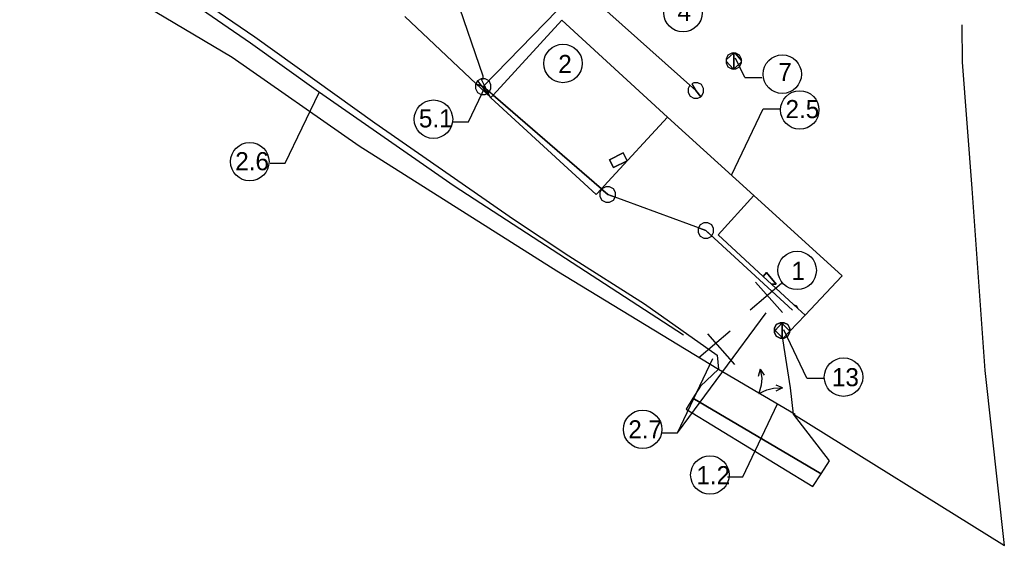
# Model space of a CAD drawing. Extents: x -438410 to -437811, y -1133174 to -1132817.
# Drawn here: x -438410 to -438308.1, y -1133171.7 to -1133117.4 of the extents above; entities that cross this region are included whole.
import ezdxf

# ---------------------------------------------------------------- set-up
doc = ezdxf.new("R2010")
doc.units = 0
for name, color, linetype in [('11 - bourané objekty', 7, 'Continuous'), ('17 - panel', 7, 'Continuous'), ('18 - asfalt', 7, 'Continuous'), ('2 - dopravní značení', 7, 'Continuous'), ('20 - popisy', 7, 'Continuous'), ('3 - ploty a brány', 7, 'Continuous'), ('4 - svodidla', 7, 'Continuous'), ('5 - obrubníky', 7, 'Continuous'), ('7 - elektro', 7, 'Continuous')]:
    doc.layers.add(name, color=color, linetype=linetype)

msp = doc.modelspace()

# ---------------------------------------------------------------- linework, layer by layer
at = {"layer": '11 - bourané objekty'}
for p, q in [((-438353.87, -1133117.4), (-438360.99, -1133125.16)), ((-438336.12, -1133120.84), (-438336.88, -1133121.51)), ((-438336.88, -1133121.51), (-438336.12, -1133120.84)), ((-438336.68, -1133121.04), (-438336.88, -1133121.44)), ((-438336.28, -1133120.84), (-438336.68, -1133121.04)), ((-438336.12, -1133120.84), (-438336.28, -1133120.84)), ((-438336.03, -1133120.76), (-438336.12, -1133120.84)), ((-438336.08, -1133120.84), (-438336.12, -1133120.84)), ((-438336.08, -1133121.49), (-438336.08, -1133120.84)), ((-438336.03, -1133120.84), (-438336.03, -1133120.76)), ((-438335.88, -1133120.84), (-438335.95, -1133120.84)), ((-438335.95, -1133120.84), (-438335.28, -1133121.58)), ((-438335.28, -1133121.58), (-438335.95, -1133120.84)), ((-438335.48, -1133121.04), (-438335.88, -1133120.84)), ((-438335.28, -1133121.44), (-438335.48, -1133121.04)), ((-438336.88, -1133121.44), (-438336.88, -1133121.51)), ((-438336.88, -1133121.67), (-438336.15, -1133122.44)), ((-438336.15, -1133122.44), (-438336.88, -1133121.67)), ((-438336.88, -1133121.67), (-438336.88, -1133121.84)), ((-438336.88, -1133121.84), (-438336.68, -1133122.24)), ((-438336.08, -1133122.44), (-438336.08, -1133121.79)), ((-438336.02, -1133122.44), (-438335.28, -1133121.74)), ((-438335.28, -1133121.74), (-438336.02, -1133122.44)), ((-438335.48, -1133122.24), (-438335.28, -1133121.84)), ((-438335.28, -1133121.58), (-438335.28, -1133121.44)), ((-438335.28, -1133121.84), (-438335.28, -1133121.74)), ((-438336.68, -1133122.24), (-438336.28, -1133122.44)), ((-438336.28, -1133122.44), (-438336.15, -1133122.44)), ((-438336.15, -1133122.44), (-438336.09, -1133122.5)), ((-438336.09, -1133122.44), (-438336.15, -1133122.44)), ((-438336.09, -1133122.5), (-438336.09, -1133122.44)), ((-438336.08, -1133122.44), (-438336.02, -1133122.44)), ((-438336.02, -1133122.44), (-438335.88, -1133122.44)), ((-438335.88, -1133122.44), (-438335.48, -1133122.24)), ((-438360.99, -1133125.16), (-438361.23, -1133125.42)), ((-438360.99, -1133125.16), (-438349.78, -1133134.87)), ((-438349.78, -1133134.87), (-438360.99, -1133125.16)), ((-438348.92, -1133131.85), (-438347.52, -1133131.15)), ((-438347.52, -1133131.15), (-438348.92, -1133131.85)), ((-438347.52, -1133131.15), (-438347.12, -1133131.95)), ((-438347.12, -1133131.95), (-438347.52, -1133131.15)), ((-438348.52, -1133132.65), (-438348.92, -1133131.85)), ((-438348.92, -1133131.85), (-438348.52, -1133132.65)), ((-438347.12, -1133131.95), (-438348.52, -1133132.65)), ((-438348.52, -1133132.65), (-438347.12, -1133131.95)), ((-438350.32, -1133135.46), (-438349.78, -1133134.87)), ((-438324.87, -1133143.87), (-438333.99, -1133135.56)), ((-438337.69, -1133139.63), (-438333.03, -1133143.93)), ((-438333.03, -1133143.93), (-438332.69, -1133143.53)), ((-438332.69, -1133143.53), (-438333.03, -1133143.93)), ((-438332.69, -1133143.53), (-438331.69, -1133144.73)), ((-438331.69, -1133144.73), (-438332.69, -1133143.53)), ((-438331.69, -1133144.73), (-438332.17, -1133144.73)), ((-438332.17, -1133144.73), (-438329.91, -1133146.81)), ((-438332.16, -1133144.73), (-438331.69, -1133144.73)), ((-438329.91, -1133146.81), (-438329.57, -1133146.97)), ((-438329.57, -1133146.97), (-438329.44, -1133147.23)), ((-438331.87, -1133149.29), (-438331.88, -1133149.31)), ((-438331.88, -1133149.31), (-438331.88, -1133149.53)), ((-438331.88, -1133149.53), (-438331.88, -1133149.71)), ((-438331.68, -1133148.91), (-438331.86, -1133149.28)), ((-438331.86, -1133149.28), (-438331.86, -1133149.3)), ((-438331.81, -1133149.53), (-438331.11, -1133148.77)), ((-438331.81, -1133149.53), (-438331.08, -1133150.25)), ((-438331.08, -1133150.25), (-438331.81, -1133149.53)), ((-438331.28, -1133148.71), (-438331.68, -1133148.91)), ((-438331.11, -1133148.71), (-438331.28, -1133148.71)), ((-438331.08, -1133148.8), (-438331.11, -1133148.77)), ((-438330.88, -1133148.71), (-438331.08, -1133148.71)), ((-438330.28, -1133149.58), (-438331.08, -1133148.8)), ((-438331.08, -1133149.36), (-438331.08, -1133148.8)), ((-438331.08, -1133148.8), (-438330.28, -1133149.58)), ((-438331.08, -1133149.51), (-438331.08, -1133149.36)), ((-438331.08, -1133149.66), (-438331.08, -1133149.51)), ((-438330.97, -1133150.31), (-438330.28, -1133149.6)), ((-438330.28, -1133149.6), (-438330.97, -1133150.31)), ((-438330.48, -1133148.91), (-438330.88, -1133148.71)), ((-438330.28, -1133149.31), (-438330.48, -1133148.91)), ((-438330.28, -1133149.58), (-438330.28, -1133149.31)), ((-438330.28, -1133149.71), (-438330.28, -1133149.6)), ((-438331.88, -1133149.71), (-438331.68, -1133150.11)), ((-438331.68, -1133150.11), (-438331.28, -1133150.31)), ((-438331.28, -1133150.31), (-438331.08, -1133150.31)), ((-438331.08, -1133150.25), (-438331.08, -1133149.66)), ((-438331.08, -1133150.25), (-438331.02, -1133150.31)), ((-438331.08, -1133150.31), (-438331.08, -1133150.25)), ((-438330.97, -1133150.31), (-438330.88, -1133150.31)), ((-438330.88, -1133150.31), (-438330.48, -1133150.11)), ((-438330.48, -1133150.11), (-438330.28, -1133149.71))]:
    msp.add_line(p, q, dxfattribs=at)
for points in [[(-438342.94, -1133127.44), (-438342.94, -1133127.44), (-438353.87, -1133117.4)], [(-438336.12, -1133120.84), (-438336.08, -1133120.84), (-438336.03, -1133120.84)], [(-438335.95, -1133120.84), (-438336.03, -1133120.84), (-438336.08, -1133120.84)], [(-438336.08, -1133120.84), (-438336.08, -1133121.49), (-438336.08, -1133121.64), (-438336.08, -1133121.79), (-438336.08, -1133122.44)], [(-438336.88, -1133121.51), (-438336.88, -1133121.59), (-438336.88, -1133121.67)], [(-438336.08, -1133121.79), (-438336.08, -1133121.64), (-438336.08, -1133121.49)], [(-438336.08, -1133121.49), (-438336.08, -1133121.49)], [(-438336.08, -1133121.79), (-438336.08, -1133121.79)], [(-438335.28, -1133121.74), (-438335.28, -1133121.67), (-438335.28, -1133121.58)], [(-438336.15, -1133122.44), (-438336.09, -1133122.44), (-438336.08, -1133122.44)], [(-438361.23, -1133125.42), (-438361.23, -1133125.42), (-438361.23, -1133125.42), (-438361.23, -1133125.42)], [(-438361.23, -1133125.42), (-438361.22, -1133125.44), (-438350.32, -1133135.45), (-438350.32, -1133135.46)], [(-438349.78, -1133134.87), (-438349.12, -1133134.15), (-438342.94, -1133127.44)], [(-438342.94, -1133127.44), (-438342.94, -1133127.44), (-438342.94, -1133127.44)], [(-438333.99, -1133135.56), (-438333.99, -1133135.56), (-438337.69, -1133139.62)], [(-438337.69, -1133139.62), (-438337.69, -1133139.63), (-438337.69, -1133139.63), (-438337.69, -1133139.63)], [(-438333.03, -1133143.93), (-438333.03, -1133143.93), (-438332.16, -1133144.72), (-438332.16, -1133144.73)], [(-438328.69, -1133147.93), (-438324.88, -1133143.88), (-438324.87, -1133143.87)], [(-438324.87, -1133143.87), (-438324.87, -1133143.87), (-438324.87, -1133143.87)], [(-438329.44, -1133147.23), (-438328.69, -1133147.92), (-438328.69, -1133147.93)], [(-438331.88, -1133149.53), (-438331.81, -1133149.53), (-438331.81, -1133149.53)], [(-438331.81, -1133149.53), (-438331.81, -1133149.53), (-438331.88, -1133149.53)], [(-438331.86, -1133149.3), (-438331.87, -1133149.29)], [(-438331.12, -1133148.77), (-438331.81, -1133149.53), (-438331.81, -1133149.53)], [(-438331.81, -1133149.53), (-438331.81, -1133149.53), (-438331.81, -1133149.53)], [(-438331.11, -1133148.77), (-438331.11, -1133148.77), (-438331.12, -1133148.77)], [(-438331.11, -1133148.77), (-438331.11, -1133148.77), (-438331.11, -1133148.71)], [(-438331.08, -1133148.71), (-438331.08, -1133148.77), (-438331.08, -1133148.8)], [(-438331.08, -1133148.8), (-438331.08, -1133149.36), (-438331.08, -1133149.51), (-438331.08, -1133149.66), (-438331.08, -1133150.25)], [(-438330.28, -1133149.6), (-438330.28, -1133149.6), (-438330.28, -1133149.58)], [(-438331.02, -1133150.31), (-438330.99, -1133150.31), (-438330.97, -1133150.31)]]:
    msp.add_lwpolyline(points, dxfattribs=at)
at = {"layer": '17 - panel'}
for p, q in [((-438362, -1133123.21), (-438364.86, -1133114.9)), ((-438370.13, -1133117.02), (-438362.75, -1133123.99)), ((-438362.75, -1133123.99), (-438362.6, -1133123.69)), ((-438362.2, -1133123.49), (-438362, -1133123.49)), ((-438362, -1133123.49), (-438362, -1133123.21))]:
    msp.add_line(p, q, dxfattribs=at)
msp.add_lwpolyline([(-438362.6, -1133123.69), (-438361.24, -1133125.42), (-438362.2, -1133123.49)], dxfattribs=at)
at = {"layer": '18 - asfalt'}
for p, q in [((-438362.75, -1133123.99), (-438370.13, -1133117.02)), ((-438385.64, -1133119.14), (-438373.21, -1133128.04)), ((-438361.23, -1133125.42), (-438362.75, -1133123.99)), ((-438373.21, -1133128.04), (-438358.87, -1133138.01)), ((-438333.99, -1133135.56), (-438342.94, -1133127.44)), ((-438349.78, -1133134.87), (-438350.32, -1133135.45)), ((-438337.69, -1133139.62), (-438333.99, -1133135.56)), ((-438358.87, -1133138.01), (-438353.15, -1133141.78)), ((-438333.03, -1133143.93), (-438337.69, -1133139.62)), ((-438353.15, -1133141.78), (-438345.32, -1133146.77)), ((-438332.17, -1133144.73), (-438333.03, -1133143.93)), ((-438329.91, -1133146.81), (-438332.17, -1133144.73)), ((-438345.32, -1133146.77), (-438337.78, -1133152.05)), ((-438329.9, -1133146.81), (-438329.91, -1133146.81)), ((-438329.44, -1133147.23), (-438329.9, -1133146.81)), ((-438328.69, -1133147.92), (-438329.44, -1133147.23)), ((-438329.44, -1133147.23), (-438329.44, -1133147.23)), ((-438330.27, -1133149.59), (-438328.69, -1133147.92)), ((-438331.88, -1133149.53), (-438331.88, -1133149.31)), ((-438331.88, -1133149.71), (-438331.88, -1133149.53)), ((-438331.86, -1133149.28), (-438331.68, -1133148.91)), ((-438331.68, -1133148.91), (-438331.28, -1133148.71)), ((-438331.08, -1133148.71), (-438330.88, -1133148.71)), ((-438330.88, -1133148.71), (-438330.48, -1133148.91)), ((-438330.48, -1133148.91), (-438330.28, -1133149.31)), ((-438330.28, -1133149.31), (-438330.28, -1133149.58)), ((-438330.28, -1133149.58), (-438330.27, -1133149.59)), ((-438331.68, -1133150.11), (-438331.88, -1133149.71)), ((-438331.28, -1133150.31), (-438331.68, -1133150.11)), ((-438330.99, -1133150.33), (-438331.02, -1133150.31)), ((-438331.02, -1133150.31), (-438331.02, -1133150.31)), ((-438330.88, -1133151.28), (-438330.99, -1133150.33)), ((-438330.22, -1133155.45), (-438330.88, -1133151.28)), ((-438337.78, -1133152.05), (-438337.65, -1133153.52)), ((-438337.65, -1133153.52), (-438339.52, -1133155.26)), ((-438339.52, -1133155.26), (-438340.32, -1133156.53)), ((-438329.9, -1133158.18), (-438330.22, -1133155.45)), ((-438340.32, -1133156.53), (-438341.02, -1133157.67)), ((-438327.05, -1133164.35), (-438340.32, -1133156.53)), ((-438340.32, -1133156.53), (-438327.05, -1133164.35)), ((-438341.02, -1133157.67), (-438327.89, -1133165.67)), ((-438326.18, -1133162.99), (-438329.9, -1133158.18)), ((-438327.05, -1133164.35), (-438326.18, -1133162.99)), ((-438327.89, -1133165.66), (-438327.05, -1133164.35))]:
    msp.add_line(p, q, dxfattribs=at)
for points in [[(-438395.97, -1133112.03), (-438394.25, -1133113.21), (-438392.35, -1133114.52), (-438385.64, -1133119.14)], [(-438350.32, -1133135.45), (-438361.22, -1133125.44), (-438361.23, -1133125.42)], [(-438342.94, -1133127.44), (-438349.12, -1133134.15), (-438349.78, -1133134.87)], [(-438331.88, -1133149.31), (-438331.87, -1133149.29), (-438331.86, -1133149.28)], [(-438331.28, -1133148.71), (-438331.11, -1133148.71), (-438331.08, -1133148.71)], [(-438331.02, -1133150.31), (-438331.08, -1133150.31), (-438331.28, -1133150.31)], [(-438327.89, -1133165.67), (-438327.89, -1133165.66)]]:
    msp.add_lwpolyline(points, dxfattribs=at)
at = {"layer": '2 - dopravní značení'}
for p, q in [((-438333.83, -1133144.52), (-438331.05, -1133147.67)), ((-438334.39, -1133147.39), (-438331.14, -1133144.61)), ((-438339.7, -1133152.32), (-438336.46, -1133149.54)), ((-438338.79, -1133149.87), (-438336.01, -1133153.02))]:
    msp.add_line(p, q, dxfattribs=at)
at = {"layer": '20 - popisy'}
for p, q in [((-438334.95, -1133123.33), (-438335.89, -1133121.36)), ((-438334.95, -1133123.33), (-438333.16, -1133123.33)), ((-438382.48, -1133132.21), (-438378.99, -1133124.91)), ((-438363.53, -1133127.94), (-438361.77, -1133124.24)), ((-438336.33, -1133133.45), (-438333.05, -1133126.58)), ((-438333.05, -1133126.58), (-438331.25, -1133126.58)), ((-438365.11, -1133127.94), (-438363.53, -1133127.94)), ((-438384.05, -1133132.21), (-438382.48, -1133132.21)), ((-438341.91, -1133160.09), (-438332.72, -1133147.69)), ((-438328.53, -1133154.43), (-438330.91, -1133149.44)), ((-438341.91, -1133160.09), (-438338.24, -1133152.4)), ((-438328.53, -1133154.43), (-438326.74, -1133154.43)), ((-438335.13, -1133164.64), (-438331.54, -1133157.11)), ((-438343.49, -1133160.09), (-438341.91, -1133160.09)), ((-438336.71, -1133164.64), (-438335.13, -1133164.64))]:
    msp.add_line(p, q, dxfattribs=at)
for centre in [(-438341.33, -1133116.64), (-438353.75, -1133121.89), (-438331.06, -1133123), (-438329.25, -1133126.7), (-438367.15, -1133127.66), (-438386.16, -1133132.05), (-438329.52, -1133143.3), (-438324.72, -1133154.34), (-438345.5, -1133159.74), (-438338.55, -1133164.46)]:
    msp.add_circle(centre, 1.99, dxfattribs=at)
at = {"layer": '3 - ploty a brány'}
for p, q in [((-438337.65, -1133153.52), (-438329.74, -1133158.18)), ((-438333.34, -1133153.53), (-438333.56, -1133154.26)), ((-438333.34, -1133153.53), (-438333.18, -1133154.44)), ((-438333.34, -1133153.53), (-438332.93, -1133154.14)), ((-438333.18, -1133154.44), (-438333.26, -1133155.16)), ((-438333.26, -1133155.16), (-438333.47, -1133156.03)), ((-438333.47, -1133156.03), (-438332.65, -1133155.67)), ((-438332.65, -1133155.67), (-438331.96, -1133155.47)), ((-438331.96, -1133155.47), (-438331.04, -1133155.46)), ((-438331.04, -1133155.46), (-438331.72, -1133155.8)), ((-438331.04, -1133155.46), (-438331.7, -1133155.16))]:
    msp.add_line(p, q, dxfattribs=at)
for points in [[(-438409.97, -1133109.05), (-438399.86, -1133114.18), (-438387.97, -1133121.25), (-438374.83, -1133130.42), (-438354.39, -1133143.33), (-438337.65, -1133153.52)], [(-438329.9, -1133158.18), (-438308.08, -1133171.74), (-438310.08, -1133153.65), (-438311.42, -1133134.84), (-438312.4, -1133121.75), (-438312.46, -1133117.91)]]:
    msp.add_lwpolyline(points, dxfattribs=at)
at = {"layer": '4 - svodidla'}
msp.add_lwpolyline([(-438402.81, -1133108.86), (-438399.19, -1133110.74), (-438386.08, -1133119.76), (-438379.06, -1133124.79), (-438365.02, -1133134.54), (-438341.28, -1133149.98)], dxfattribs=at)
at = {"layer": '5 - obrubníky'}
msp.add_line((-438333.99, -1133135.56), (-438342.94, -1133127.44), dxfattribs=at)
at = {"layer": '7 - elektro'}
for p, q in [((-438362, -1133124.29), (-438352.01, -1133113.98)), ((-438352.01, -1133113.98), (-438340, -1133124.68)), ((-438362.76, -1133124.01), (-438362.8, -1133124.09)), ((-438362.8, -1133124.09), (-438362.8, -1133124.49)), ((-438362.6, -1133123.69), (-438362.76, -1133124.01)), ((-438362, -1133124.29), (-438362.76, -1133124.01)), ((-438362.76, -1133124.01), (-438362, -1133124.29)), ((-438362.2, -1133123.49), (-438362.6, -1133123.69)), ((-438361.4, -1133123.69), (-438361.8, -1133123.49)), ((-438361.2, -1133124.09), (-438361.4, -1133123.69)), ((-438361.2, -1133124.49), (-438361.2, -1133124.09)), ((-438340.62, -1133124.13), (-438340.8, -1133124.48)), ((-438340, -1133124.68), (-438340.62, -1133124.13)), ((-438340.2, -1133123.88), (-438340.42, -1133124)), ((-438340.42, -1133124), (-438340, -1133124.68)), ((-438339.4, -1133124.08), (-438339.8, -1133123.88)), ((-438339.2, -1133124.48), (-438339.4, -1133124.08)), ((-438362.8, -1133124.49), (-438362.6, -1133124.89)), ((-438362.6, -1133124.89), (-438362.2, -1133125.09)), ((-438362.2, -1133125.09), (-438361.8, -1133125.09)), ((-438349.12, -1133135.45), (-438362, -1133124.29)), ((-438361.39, -1133124.87), (-438362, -1133124.29)), ((-438362, -1133124.29), (-438361.38, -1133124.85)), ((-438361.8, -1133125.09), (-438361.4, -1133124.89)), ((-438361.4, -1133124.89), (-438361.39, -1133124.87)), ((-438361.38, -1133124.85), (-438361.2, -1133124.49)), ((-438340.8, -1133124.48), (-438340.8, -1133124.88)), ((-438340.8, -1133124.88), (-438340.6, -1133125.28)), ((-438339.48, -1133125.33), (-438340, -1133124.68)), ((-438340, -1133124.68), (-438339.48, -1133125.33)), ((-438339.4, -1133125.28), (-438339.2, -1133124.88)), ((-438339.2, -1133124.88), (-438339.2, -1133124.48)), ((-438340.6, -1133125.28), (-438340.2, -1133125.48)), ((-438340.2, -1133125.48), (-438339.8, -1133125.48)), ((-438339.8, -1133125.48), (-438339.48, -1133125.33)), ((-438339.48, -1133125.33), (-438339.4, -1133125.28)), ((-438349.75, -1133134.9), (-438349.92, -1133135.25)), ((-438349.92, -1133135.25), (-438349.92, -1133135.65)), ((-438349.72, -1133134.85), (-438349.75, -1133134.9)), ((-438349.12, -1133135.45), (-438349.75, -1133134.9)), ((-438349.75, -1133134.9), (-438349.12, -1133135.45)), ((-438349.32, -1133134.65), (-438349.72, -1133134.85)), ((-438348.52, -1133134.85), (-438348.92, -1133134.65)), ((-438348.32, -1133135.25), (-438348.52, -1133134.85)), ((-438348.32, -1133135.65), (-438348.32, -1133135.25)), ((-438349.92, -1133135.65), (-438349.72, -1133136.05)), ((-438349.72, -1133136.05), (-438349.32, -1133136.25)), ((-438349.32, -1133136.25), (-438348.92, -1133136.25)), ((-438338.96, -1133139.17), (-438349.12, -1133135.45)), ((-438348.36, -1133135.72), (-438349.12, -1133135.45)), ((-438349.12, -1133135.45), (-438348.36, -1133135.72)), ((-438348.92, -1133136.25), (-438348.52, -1133136.05)), ((-438348.52, -1133136.05), (-438348.36, -1133135.72)), ((-438348.36, -1133135.72), (-438348.32, -1133135.65)), ((-438339.16, -1133138.37), (-438339.56, -1133138.57)), ((-438338.36, -1133138.57), (-438338.76, -1133138.37)), ((-438339.72, -1133138.89), (-438339.76, -1133138.97)), ((-438339.76, -1133138.97), (-438339.76, -1133139.37)), ((-438339.76, -1133139.37), (-438339.56, -1133139.77)), ((-438339.56, -1133138.57), (-438339.72, -1133138.89)), ((-438338.96, -1133139.17), (-438339.72, -1133138.89)), ((-438339.72, -1133138.89), (-438338.96, -1133139.17)), ((-438329.99, -1133147.42), (-438338.96, -1133139.17)), ((-438338.35, -1133139.75), (-438338.96, -1133139.17)), ((-438338.96, -1133139.17), (-438338.35, -1133139.74)), ((-438338.16, -1133138.97), (-438338.36, -1133138.57)), ((-438338.35, -1133139.74), (-438338.16, -1133139.37)), ((-438338.16, -1133139.37), (-438338.16, -1133138.97)), ((-438339.56, -1133139.77), (-438339.16, -1133139.97)), ((-438339.16, -1133139.97), (-438338.76, -1133139.97)), ((-438338.76, -1133139.97), (-438338.36, -1133139.77)), ((-438338.36, -1133139.77), (-438338.35, -1133139.75))]:
    msp.add_line(p, q, dxfattribs=at)
for points in [[(-438361.8, -1133123.49), (-438362, -1133123.49), (-438362.2, -1133123.49)], [(-438339.8, -1133123.88), (-438340, -1133123.88), (-438340.2, -1133123.88)], [(-438348.92, -1133134.65), (-438349.12, -1133134.65), (-438349.32, -1133134.65)], [(-438338.76, -1133138.37), (-438338.96, -1133138.37), (-438339.16, -1133138.37)]]:
    msp.add_lwpolyline(points, dxfattribs=at)

# ---------------------------------------------------------------- texts
at = {"layer": '20 - popisy'}
for s, height, p in [('4', 1.88, (-438341.9, -1133117.49)), ('2', 1.88, (-438354.24, -1133122.89)), ('7', 1.88, (-438331.47, -1133123.71)), ('2.5', 1.875, (-438330.72, -1133127.55)), ('5.1', 1.875, (-438368.66, -1133128.51)), ('2.6', 1.875, (-438387.66, -1133132.94)), ('1', 1.88, (-438330.11, -1133144.29)), ('13', 1.875, (-438325.92, -1133155.28)), ('2.7', 1.875, (-438346.99, -1133160.68)), ('1.2', 1.875, (-438339.94, -1133165.42))]:
    msp.add_text(s, height=height, dxfattribs=at).set_placement(p)

doc.saveas('drawing.dxf')
